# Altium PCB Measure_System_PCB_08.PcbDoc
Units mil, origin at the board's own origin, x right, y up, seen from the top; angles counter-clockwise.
Board outline 6000 x 4000 mil, 2 copper layers (Top Layer, Bottom Layer); 44 components, 29 nets, 115 pads, 0 vias.
Unrouted connection lines stored in the file: 4.
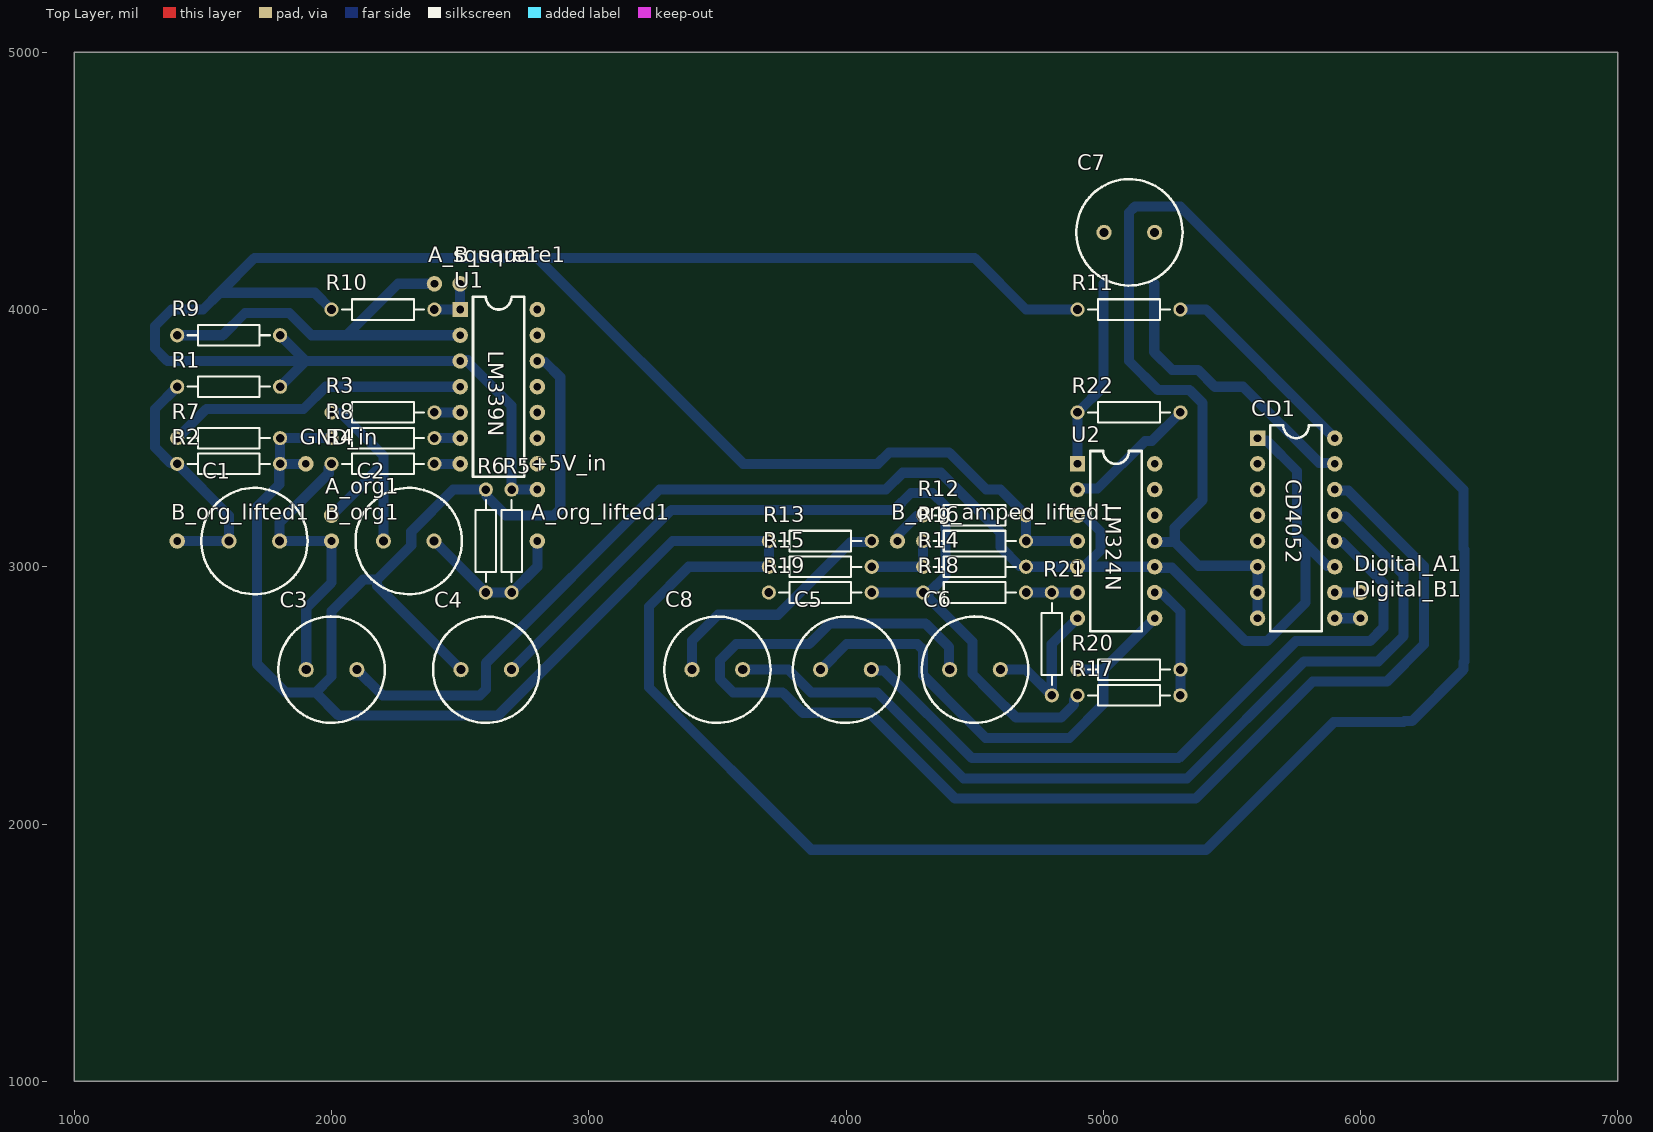
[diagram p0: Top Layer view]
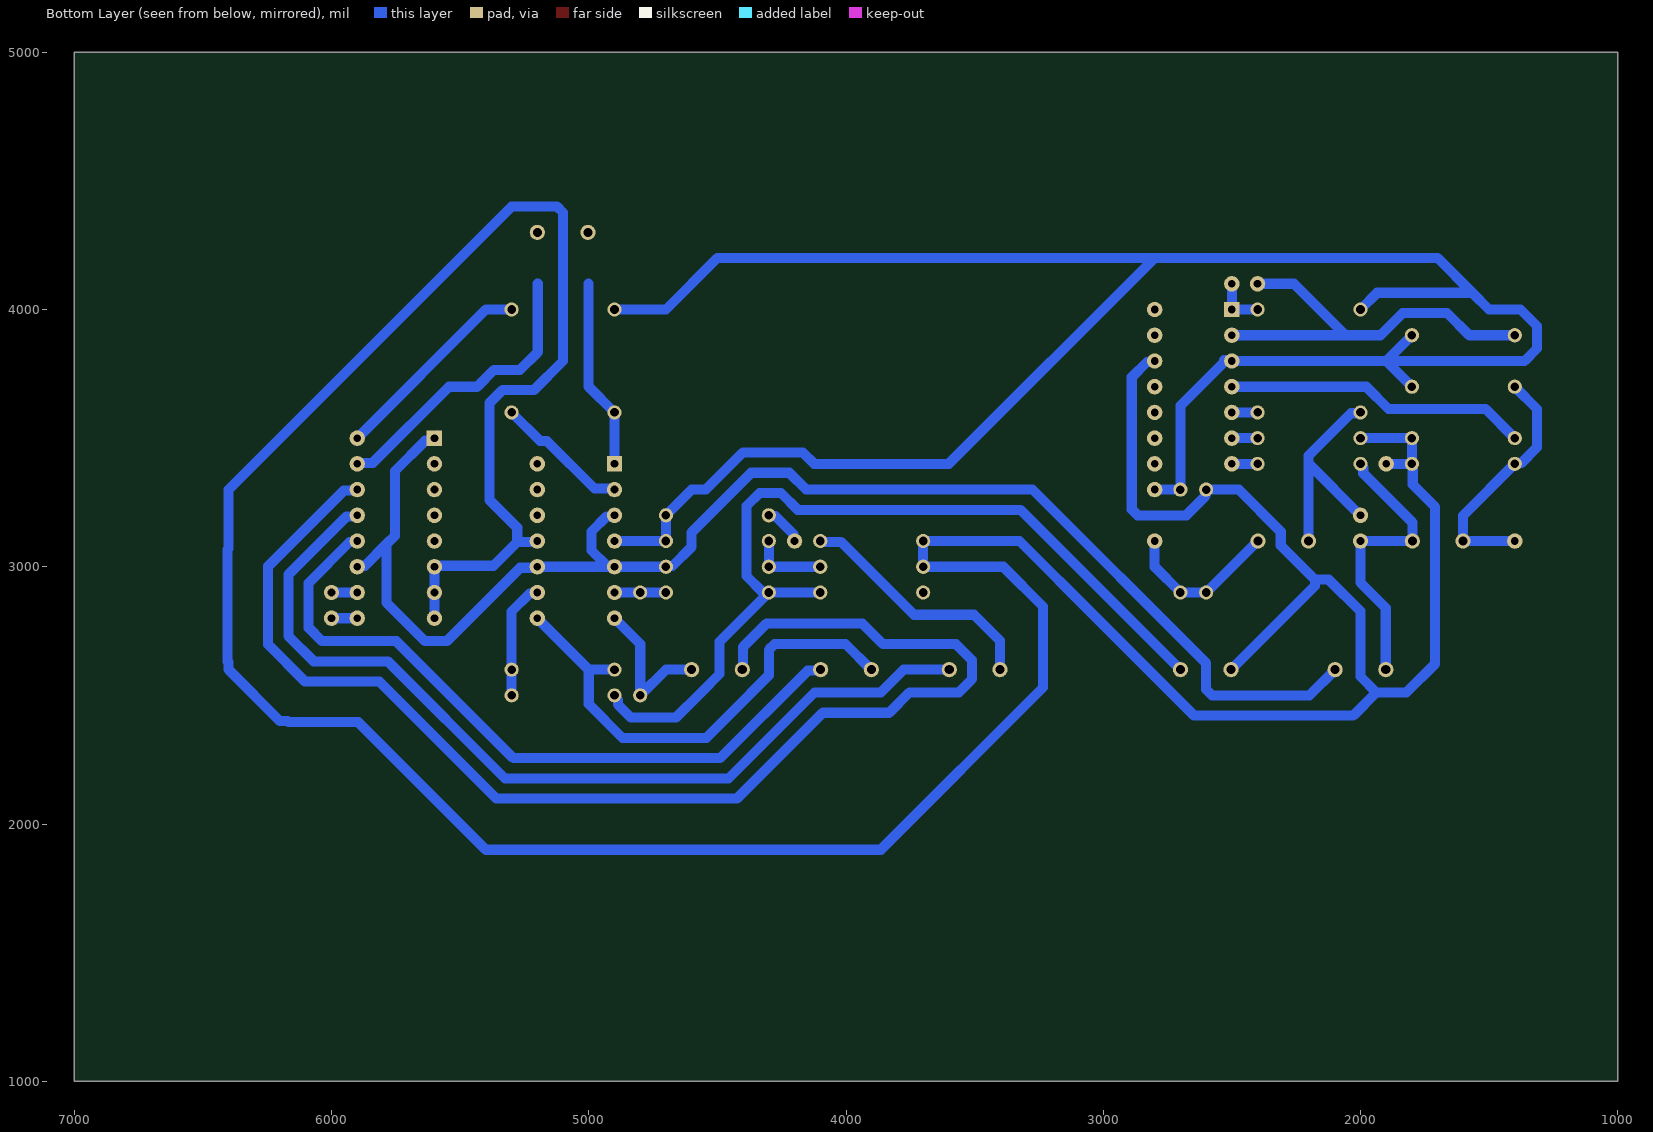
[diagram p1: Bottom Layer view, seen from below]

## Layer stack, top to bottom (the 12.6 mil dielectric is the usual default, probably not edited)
Top Solder: solder mask 0.4, Solder Resist, Dk 3.5
Top Layer: signal copper 1.4
Dielectric 1: dielectric 12.6, FR-4, Dk 4.8
Bottom Layer: signal copper 1.4
Bottom Solder: solder mask 0.4, Solder Resist, Dk 3.5

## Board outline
1000,1000 7000,1000 7000,5000 1000,5000

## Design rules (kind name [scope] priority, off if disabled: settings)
Clearance [All] p1: gap=39.37 ignorepadtopadclearanceinfootprint=FALSE
PolygonConnect [All] p1: connectstyle=Relief reliefconductorwidth=10 reliefentries=4 polygonreliefangle="90 Angle" airgapwidth=10
RoomDefinition Measure_System_Main [InComponentClass('Measure_System_Main')] p1: confinementstyle=ConfineIn formatcopy=TRUE lockcomponents=FALSE outline 0,0 2000,0 2000,1000 0,1000
RoutingVias [All] p1: holewidth=28 width=50 viastyle="Through Hole" minholewidth=28 minwidth=50 maxholewidth=28 maxwidth=50
SolderMaskExpansion [All] p1: expansion=4 istentingtop=FALSE
Width [All] p1: maxlimit=393.7 minlimit=19.68 preferedwidth=39.37 toplayer_maxwidth=393.7 bottomlayer_prefwidth=39.37 minimp=50.000000 maximp=50.000000 favimp=50.000000
30 further rules are at their usual default settings.

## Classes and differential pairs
component class Part_Square: C1 C2 R1 R2 R3 R4 R5 R6 R7 R8 R9 R10 U1
component class Part_PGA: C3 C4 C5 C6 C7 C8 CD1 R11 R12 R13 R14 R15 R16 R17 R18 R19 R20 R21 R22 U2
component class Measure_System_Main: +5V_in A_org1 A_org_lifted1 A_square1 B_org1 B_org_amped_lifted1 B_org_lifted1 B_square1 Digital_A1 Digital_B1 GND_in

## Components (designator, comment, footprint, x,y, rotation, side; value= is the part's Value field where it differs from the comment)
+5V_in "Hole" Hole 2800,3300 r90 top
A_org1 "Hole" Hole 2000,3200 r90 top
A_org_lifted1 "Hole" Hole 2800,3100 r90 top
A_square1 "Hole" Hole 2400,4100 r90 top
B_org1 "Hole" Hole 2000,3100 r90 top
B_org_amped_lifted1 "Hole" Hole 4200,3100 r90 top
B_org_lifted1 "Hole" Hole 1400,3100 r90 top
B_square1 "Hole" Hole 2500,4100 r90 top
C1 "Cap Pol1" RB5-10.5 1700,3100 r180 top value=10u
C2 "Cap Pol1" RB5-10.5 2300,3100 r0 top value=10u
C3 "Cap Pol1" RB5-10.5 2000,2600 r0 top value=10u
C4 "Cap Pol1" RB5-10.5 2601.57,2600 r0 top value=10u
C5 "Cap Pol1" RB5-10.5 4000,2600 r0 top value=10u
C6 "Cap Pol1" RB5-10.5 4501.57,2600 r180 top value=10u
C7 "Cap Pol1" RB5-10.5 5101.57,4300 r0 top value=10u
C8 "Cap Pol1" RB5-10.5 3500,2600 r180 top value=10u
CD1 "CD4052" CD4052 5600,3500 r0 top
Digital_A1 "Hole" Hole 6000,2900 r90 top
Digital_B1 "Hole" Hole 6000,2800 r90 top
GND_in "Hole" Hole 1900,3400 r90 top
R1 "Res2" AXIAL-0.4 1600,3700 r0 top value=100k
R2 "Res2" AXIAL-0.4 1600,3400 r180 top value=100k
R3 "Res2" AXIAL-0.4 2200,3600 r180 top value=1k
R4 "Res2" AXIAL-0.4 2200,3400 r180 top value=1k
R5 "Res2" AXIAL-0.4 2700,3100 r90 top value=100k
R6 "Res2" AXIAL-0.4 2600,3100 r270 top value=100k
R7 "Res2" AXIAL-0.4 1600,3500 r180 top value=10k
R8 "Res2" AXIAL-0.4 2200,3500 r180 top value=10k
R9 "Res2" AXIAL-0.4 1600,3900 r180 top value=10k
R10 "Res2" AXIAL-0.4 2200,4000 r180 top value=10k
R11 "Res2" AXIAL-0.4 5100,4000 r180 top value=200
R12 "Res2" AXIAL-0.4 4500,3200 r0 top value=100k
R13 "Res2" AXIAL-0.4 3900,3100 r0 top value=100k
R14 "Res2" AXIAL-0.4 4500,3000 r0 top value=100k
R15 "Res2" AXIAL-0.4 3900,3000 r0 top value=100k
R16 "Res2" AXIAL-0.4 4500,3100 r180 top value=100k
R17 "Res2" AXIAL-0.4 5100,2500 r0 top value=50k
R18 "Res2" AXIAL-0.4 4500,2900 r0 top value=24k
R19 "Res2" AXIAL-0.4 3900,2900 r180 top value=12k
R20 "Res2" AXIAL-0.4 5100,2600 r180 top value=100k
R21 "Res2" AXIAL-0.4 4800,2700 r270 top value=100k
R22 "Res2" AXIAL-0.4 5100,3600 r180 top value=100k
U1 "LM339N" LM339N 2500,4000 r0 top
U2 "LM324N" LM324N 4900,3400 r0 top

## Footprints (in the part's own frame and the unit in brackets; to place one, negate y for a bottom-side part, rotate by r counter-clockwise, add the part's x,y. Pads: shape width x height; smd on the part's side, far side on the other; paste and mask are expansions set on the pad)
AXIAL-0.4 [mm] "Axial Device, Thru-Hole; 2 Leads; 0.4 in Pin Spacing"
  round 1.4 hole 0.85: 1(-5.08,0) 2(5.08,0)
  silkscreen extent -4.06,-1.02 4.06,1.02
CD4052 [mil]
  rect 60x60 hole 30: 1(0,0)
  round 60 hole 30 mask+4: 2(0,-100) 3(0,-200) 4(0,-300) 5(0,-400) 6(0,-500) 7(0,-600) 8(0,-700) 9(300,-700) 10(300,-600) 11(300,-500) 12(300,-400) 13(300,-300) 14(300,-200) 15(300,-100) 16(300,0)
  silkscreen extent 50,-750 250,50
Hole [mil]
  round 60 hole 30 mask+4: 1(0,0)
LM324N [mil]
  rect 60x60 hole 30: 1(0,0)
  round 60 hole 30 mask+4: 2(0,-100) 3(0,-200) 4(0,-300) 5(0,-400) 6(0,-500) 7(0,-600) 8(300,-600) 9(300,-500) 10(300,-400) 11(300,-300) 12(300,-200) 13(300,-100) 14(300,0)
  silkscreen extent 50,-650 250,50
LM339N [mil]
  rect 60x60 hole 30: 1(0,0)
  round 60 hole 30 mask+4: 2(0,-100) 3(0,-200) 4(0,-300) 5(0,-400) 6(0,-500) 7(0,-600) 8(300,-600) 9(300,-500) 10(300,-400) 11(300,-300) 12(300,-200) 13(300,-100) 14(300,0)
  silkscreen extent 50,-650 250,50
RB5-10.5 [mm] "Capacitor (Radial); 2 Leads"
  round 1.5 hole 0.9: 1(-2.5,0) 2(2.5,0)
  silkscreen extent -5.25,-5.25 5.25,5.25

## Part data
C1 C2 C3 C4 C5 C6 C7 C8: "Polarized Capacitor (Radial)"
R1 R2 R3 R4 R5 R6 R7 R8 R9 R10 R11 R12 R13 R14 R15 R16 R17 R18 R19 R20 R21 R22: "Resistor"

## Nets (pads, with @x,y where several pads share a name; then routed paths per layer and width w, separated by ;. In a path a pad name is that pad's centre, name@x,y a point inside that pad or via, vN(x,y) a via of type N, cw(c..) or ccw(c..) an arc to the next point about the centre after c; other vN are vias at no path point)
+5: +5V_in.1 R1.2 R5.2 R9.1 R10.2 R11.2 R12.2 R16.1 U1.3 U2.4 | length 9166.3
  Bottom Layer w39.37: R1.2 1900,3800 ; R9.1 1900,3800 ; R10.2 1934.65,4065.35 1565.35,4065.35 ; 2529.89,3796.05 2700,3625.94 R5.2 +5V_in.1 ; 2529.89,3803.95 2503.95,3803.95 U1.3 1900,3800 ; U2.4 R16.1 R12.2 4600,3300 4545.2,3300 4401.11,3444.09 4167.79,3444.09 4123.7,3400 3600,3400 2800,4200 ; R11.2 4700,4000 4500,4200 2800,4200 ; 1565.35,4065.35 1700,4200 2800,4200 ; 1565.35,4065.35 1500,4000 1377.51,4000 1313.39,3935.88 1313.39,3848.43 1361.82,3800 1900,3800
B_org: B_org1.1 C1.1 C3.1 R4.2 | length 1125.8
  Bottom Layer w39.37: C3.1 1901.57,2839.78 2000,2938.2 B_org1.1 C1.1 1798.43,3172.48 1989.06,3363.11 1989.06,3384.79 2000,3395.74 R4.2
B_org_amp_1: C3.2 CD1.1 CD1.11 R14.2 U2.3 U2.5 U2.10 | length 5682.4
  Bottom Layer w39.37: C3.2 2198.43,2500 2576.94,2500 2600,2523.06 2600,2625.27 3274.73,3300 4154.8,3300 4220.15,3365.35 4368.49,3365.35 4600,3133.85 4600,3077.51 4674.5,3003.01 4696.99,3003.01 R14.2 U2.5 U2.10 5203.95,2996.05 5266.65,2996.05 5551.76,2710.94 5636.89,2710.94 5787.03,2861.09 5787.03,3087.03 ; U2.3 4903.95,3196.05 4929.89,3196.05 4989.06,3136.89 4989.06,3063.11 4929.89,3003.95 ; CD1.1@5589.69,3510.32 5610.31,3489.68 5636.26,3489.68 5753.5,3372.44 5753.5,3120.56 5787.03,3087.03 ; CD1.11 5896.05,3003.95 5870.11,3003.95 5787.03,3087.03
B_org_amp_2.5: C5.2 CD1.12 | length 2773.6
  Bottom Layer w39.37: C5.2 4102.19,2596.23 4149.19,2596.23 4489.52,2255.91 5293.2,2255.91 5748.24,2710.94 6036.89,2710.94 6089.06,2763.11 6089.06,2936.89 5929.89,3096.05 5903.95,3096.05 CD1.12
B_org_amp_5: C6.2 CD1.14 | length 5101.2
  Bottom Layer w39.37: C6.2 4399.71,2603.44 4399.71,2688.58 4309.55,2778.74 3935.5,2778.74 3856.76,2700 3573.15,2700 3509.84,2636.69 3509.84,2563.31 3515.67,2557.48 3561.73,2511.42 3753.53,2511.42 3832.27,2432.68 4090.03,2432.68 4424.29,2098.43 5358.43,2098.43 5813.47,2553.46 6102.12,2553.46 6246.54,2697.88 6246.54,3002.12 5952.6,3296.05 5903.95,3296.05 CD1.14
B_org_amp_10: C7.2 CD1.15 | length 1147.2
  Bottom Layer w39.37: 5198.43,4100 5198.43,3834.31 5267.38,3765.35 5368.49,3765.35 5433.85,3700 5543.52,3700 5839.57,3403.95 5896.05,3403.95 CD1.15
B_org_amped: C8.1 CD1.13 | length 3576
  Bottom Layer w39.37: C8.1 3776.3,2600 3864.88,2511.42 4122.65,2511.42 4456.9,2177.17 5325.82,2177.17 5780.86,2632.2 6069.5,2632.2 6167.8,2730.5 6167.8,2969.5 5941.25,3196.05 5903.95,3196.05 CD1.13
Digital_A: CD1.10 Digital_A1.1 | length 100
  Bottom Layer w39.37: CD1.10 Digital_A1.1
Digital_B: CD1.9 Digital_B1.1 | length 100
  Bottom Layer w39.37: CD1.9 Digital_B1.1
GND: C4.1 CD1.6 CD1.7 CD1.8 GND_in.1 R2.1 R6.1 R7.1 R8.2 R13.1 R15.1 U1.12 U2.11 | length 15466.1
  Bottom Layer w39.37: GND_in.1 R2.1 ; R8.2 R7.1 R2.1 ; C4.1 2176.85,2926.3 2176.85,2950 ; R6.1 2473.15,3300 2309.84,3136.69 2309.84,3082.99 2176.85,2950 ; R6.1@2603.01,3274.5 2677.51,3200 2865.99,3200 2889.06,3223.06 2889.06,3736.89 2829.89,3796.05 2803.95,3796.05 U1.12 ; U2.11 5203.95,3096.05 5278,3096.05 ; CD1.8 CD1.7 CD1.6 5596.05,3003.95 5370.11,3003.95 5278,3096.05 ; R2.1 1796.99,3396.99 1796.99,3319.48 1709.84,3232.33 1709.84,2623.06 1821.49,2511.42 1938.27,2511.42 ; 1938.27,2511.42 2028.42,2421.26 2646.53,2421.26 3021.18,2795.91 3325.27,3100 R13.1 R15.1 3388.64,3000 3234.25,2845.61 3234.25,2530.69 3864.94,1900 5400,1900 5895.98,2395.98 6167.35,2395.98 6171.36,2400 6200,2400 6400,2600 6400,2628.64 6404.02,2632.65 6404.02,3067.35 6400,3071.36 6400,3300 5300,4400 5123.06,4400 5100,4376.94 5100,3800 5213.39,3686.61 5335.88,3686.61 5386.61,3635.88 5386.61,3260.67 5278,3152.06 5278,3096.05 ; 1938.27,2511.42 2000,2573.15 2000,2826.85 2123.15,2950 2176.85,2950
NetA_org1_1: A_org1.1 C2.1 R3.2 | length 887.7
  Bottom Layer w39.37: A_org1.1 2001.57,3200 2201.57,3400 ; R3.2 2003.01,3596.99 2036.86,3596.99 2201.57,3432.27 2201.57,3400 ; C2.1 2201.57,3400
NetA_org_lifted1_1: A_org_lifted1.1 C2.2 R5.1 R6.2 | length 625.8
  Bottom Layer w39.37: C2.2 2399.21,3100 2599.21,2900 R6.2 R5.1 2800,3000 A_org_lifted1.1
NetA_square1_1: A_square1.1 R9.2 U1.2 | length 1596.1
  Bottom Layer w39.37: R9.2 1576.76,3900 1663.38,3986.61 1835.88,3986.61 1922.49,3900 2058.45,3900 ; A_square1.1 2258.45,4100 2058.45,3900 ; U1.2 2058.45,3900
NetB_org_amped_lifted1_1: B_org_amped_lifted1.1 C8.2 R12.1 R13.2 | length 1126.3
  Bottom Layer w39.37: C8.2 3401.57,2712.93 3502.03,2813.39 3735.88,2813.39 4019.48,3096.99 4096.99,3096.99 R13.2 ; B_org_amped_lifted1.1 4203.95,3103.95 4203.95,3126.44 4274.5,3196.99 4296.99,3196.99 R12.1
NetB_org_lifted1_1: B_org_lifted1.1 C1.2 R1.1 R2.2 | length 943.2
  Bottom Layer w39.37: R2.2@1374.5,3403.01 1313.39,3464.12 1313.39,3613.39 R1.1 ; B_org_lifted1.1 C1.2 1601.57,3198.43 R2.2
NetB_square1_1: B_square1.1 R10.1 U1.1 | length 200
  Bottom Layer w39.37: R10.1 U1.1 B_square1.1
NetC4_2: C4.2 R17.1 R18.1 R19.1 | length 3501
  Bottom Layer w39.37: C4.2 3321.26,3221.26 4187.41,3221.26 4252.77,3286.61 4335.88,3286.61 4386.61,3235.88 4386.61,2964.12 4325.5,2903.01 4303.01,2903.01 R18.1 ; R19.1 R18.1 ; R17.1 4900,2495.74 4886.61,2482.35 4886.61,2464.12 4835.88,2413.39 4661.34,2413.39 4563.31,2511.42 4491.73,2582.99 4491.73,2708.27 R18.1
NetC5_1: C5.1 R20.2 U2.8 | length 1920.4
  Bottom Layer w39.37: C5.1 4001.57,2700 4276.94,2700 4300,2676.94 4300,2577.87 4445.2,2432.68 4543.23,2334.65 4868.49,2334.65 5000,2466.15 5000,2600 ; R20.2 5000,2600 ; U2.8 5000,2600
NetC6_1: C6.1 R21.2 U2.7 | length 582.8
  Bottom Layer w39.37: C6.1 4700,2600 R21.2 4800,2700 U2.7
NetC7_1: C7.1 R22.2 U2.1 | length 742.1
  Bottom Layer w39.37: U2.1 R22.2 5001.57,3701.57 5001.57,4100
NetCD1_16: CD1.16 R11.1 | length 807.1
  Bottom Layer w39.37: R11.1 5400,4000 CD1.16
NetR3_1: R3.1 U1.5 | length 100
  Bottom Layer w39.37: R3.1 U1.5
NetR4_1: R4.1 U1.7 | length 100
  Bottom Layer w39.37: R4.1 U1.7
NetR7_2: R7.2 U1.4 | length 1182.8
  Bottom Layer w39.37: R7.2 1513.39,3613.39 1890.89,3613.39 1977.51,3700 U1.4
NetR8_1: R8.1 U1.6 | length 100
  Bottom Layer w39.37: R8.1 U1.6
NetR14_1: R14.1 R15.2 R16.2 | length 300
  Bottom Layer w39.37: R15.2 R14.1 R16.2
NetR17_2: R17.2 R20.1 U2.9 | length 456.6
  Bottom Layer w39.37: U2.9 5203.95,2896.05 5229.89,2896.05 5300,2825.94 R20.1 R17.2
NetR18_2: R18.2 R21.1 U2.6 | length 205.6
  Bottom Layer w39.37: R18.2 R21.1 U2.6 U2.6@4896.05,2896.05
NetR19_2: R19.2 R22.1 U2.2 | length 524.3
  Bottom Layer w39.37: U2.2 4903.95,3303.95 4978,3303.95 5163.11,3489.06 5189.06,3489.06 R22.1
pads on no net: CD1.2 CD1.3 CD1.4 CD1.5 U1.8 U1.9 U1.10 U1.11 U1.13 U1.14 U2.12 U2.13 U2.14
